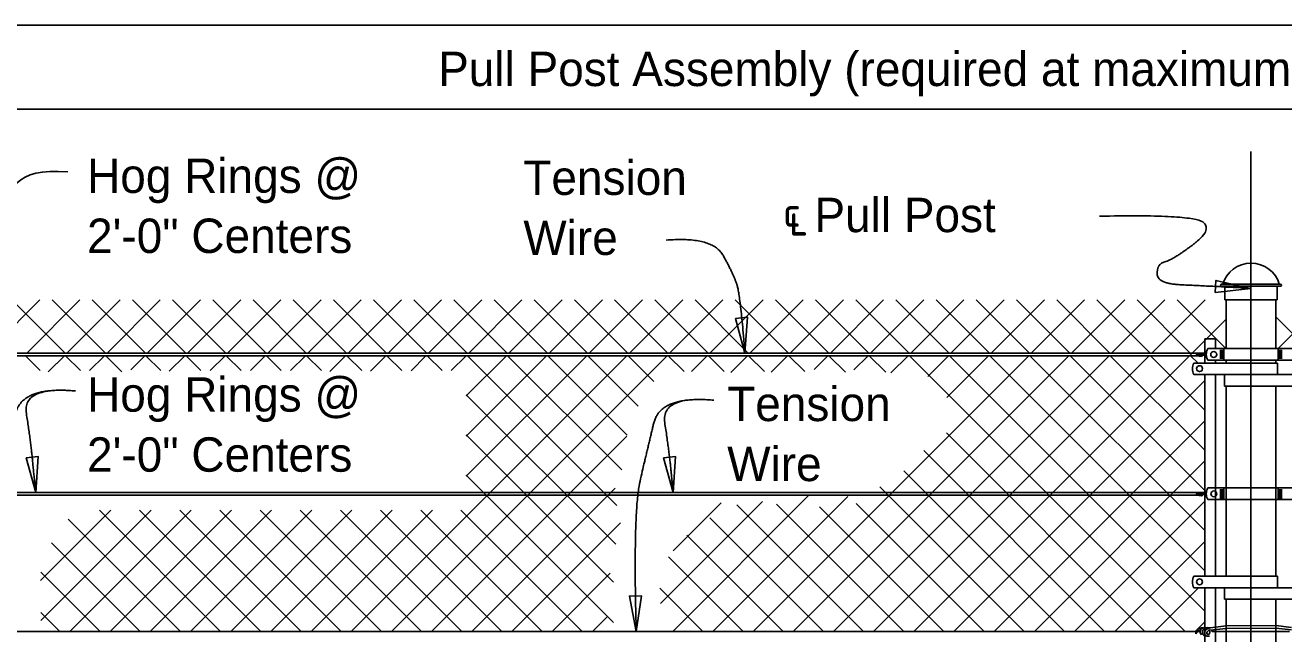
# Model space of a CAD drawing. Extents: x 0 to 41.2, y 0 to 26.
# Drawn here: x 5.02 to 12.4, y 22.39 to 25.96 of the extents above; entities that cross this region are included whole.
import ezdxf

# ---------------------------------------------------------------- set-up
doc = ezdxf.new("R2010")
doc.units = 0
for name, color, linetype in [('ActivePts-ConstElements', 7, 'Continuous'), ('CL_Major', 7, 'Continuous'), ('Dimension', 7, 'Continuous'), ('Miscellaneous', 7, 'Continuous'), ('Miscellaneous1', 7, 'Continuous'), ('SteelMisc', 7, 'Continuous'), ('SteelMisc_h', 7, 'Continuous'), ('TextStructures', 7, 'Continuous')]:
    doc.layers.add(name, color=color, linetype=linetype)

msp = doc.modelspace()

# ---------------------------------------------------------------- linework, layer by layer
at = {"layer": 'ActivePts-ConstElements'}
msp.add_lwpolyline([(0, 0), (41.2106, 0), (41.2106, 25.96), (0, 25.96)], close=True, dxfattribs=at)
at = {"layer": 'CL_Major'}
msp.add_line((12.2062, 25.2199), (12.2062, 14.8548), dxfattribs=at)
at = {"layer": 'Dimension'}
msp.add_line((2.2062, 25.4682), (22.2062, 25.4682), dxfattribs=at)
for points in [[(12.2062, 24.4166), (12.0002, 24.4632), (11.9964, 24.3927)], [(9.238, 24.0366), (9.2538, 24.2472), (9.1835, 24.2406)], [(5.0788, 23.219), (5.0926, 23.4298), (5.0224, 23.4226)], [(8.8174, 23.219), (8.8313, 23.4298), (8.7611, 23.4226)], [(8.6004, 22.4048), (8.6312, 22.6137), (8.5607, 22.6122)]]:
    msp.add_lwpolyline(points, close=True, dxfattribs=at)
for points, degree in [([(5.2657, 25.0995), (4.9524, 25.1279), (4.8838, 24.8459), (4.8116, 24.5363), (4.8088, 24.0365)], 3), ([(11.3168, 24.8403), (11.8625, 24.8501), (11.985, 24.7612), (11.7408, 24.5799), (11.6559, 24.5616), (11.6559, 24.4437), (11.934, 24.4315), (12.2063, 24.4166)], 2), ([(8.7761, 24.6996), (9.0478, 24.722), (9.174, 24.4948), (9.2108, 24.3733), (9.238, 24.0365)], 2), ([(5.3115, 23.815), (4.9982, 23.8433), (4.9198, 23.5211), (4.8367, 23.1628), (4.8566, 22.4048)], 2), ([(5.3115, 23.815), (4.9982, 23.8433), (5.0481, 23.5211), (5.0667, 23.326), (5.0788, 23.219)], 2), ([(9.0561, 23.7607), (8.7428, 23.789), (8.6644, 23.4668), (8.5813, 23.1085), (8.6004, 22.4048)], 2), ([(9.0561, 23.7607), (8.7428, 23.789), (8.7927, 23.4668), (8.8113, 23.2717), (8.8174, 23.219)], 2)]:
    msp.add_open_spline(points, degree=degree, dxfattribs=at)
at = {"layer": 'Miscellaneous'}
for p, q in [((5.1017, 24.349), (4.7948, 24.0422)), ((5.2507, 24.0365), (4.9382, 24.349)), ((5.3374, 24.349), (5.0249, 24.0365)), ((5.4864, 24.0365), (5.1739, 24.349)), ((5.5731, 24.349), (5.2606, 24.0365)), ((5.7221, 24.0365), (5.4096, 24.349)), ((5.8088, 24.349), (5.4963, 24.0365)), ((5.9579, 24.0365), (5.6453, 24.349)), ((6.0445, 24.349), (5.732, 24.0365)), ((6.1936, 24.0365), (5.881, 24.349)), ((6.2802, 24.349), (5.9677, 24.0365)), ((6.4293, 24.0365), (6.1167, 24.349)), ((6.5159, 24.349), (6.2034, 24.0365)), ((6.665, 24.0365), (6.3524, 24.349)), ((6.7516, 24.349), (6.4391, 24.0365)), ((6.9007, 24.0365), (6.5881, 24.349)), ((6.9873, 24.349), (6.6748, 24.0365)), ((7.1364, 24.0365), (6.8238, 24.349)), ((7.223, 24.349), (6.9105, 24.0365)), ((7.3721, 24.0365), (7.0595, 24.349)), ((7.4587, 24.349), (7.1462, 24.0365)), ((7.6078, 24.0365), (7.2952, 24.349)), ((7.6944, 24.349), (7.3819, 24.0365)), ((7.8435, 24.0365), (7.5309, 24.349)), ((7.9301, 24.349), (7.6176, 24.0365)), ((8.0792, 24.0365), (7.7666, 24.349)), ((8.1658, 24.349), (7.8533, 24.0365)), ((8.3149, 24.0365), (8.0023, 24.349)), ((8.4015, 24.349), (8.089, 24.0365)), ((8.5506, 24.0365), (8.238, 24.349)), ((8.6372, 24.349), (8.3247, 24.0365)), ((8.7863, 24.0365), (8.4737, 24.349)), ((8.8729, 24.349), (8.5604, 24.0365)), ((9.022, 24.0365), (8.7094, 24.349)), ((9.1086, 24.349), (8.7961, 24.0365)), ((9.2577, 24.0365), (8.9451, 24.349)), ((9.3443, 24.349), (9.0318, 24.0365)), ((9.4934, 24.0365), (9.1808, 24.349)), ((9.58, 24.349), (9.2675, 24.0365)), ((9.7291, 24.0365), (9.4166, 24.349)), ((9.8157, 24.349), (9.5032, 24.0365)), ((9.9648, 24.0365), (9.6523, 24.349)), ((10.0514, 24.349), (9.7389, 24.0365)), ((10.2005, 24.0365), (9.888, 24.349)), ((10.2871, 24.349), (9.9746, 24.0365)), ((10.4362, 24.0365), (10.1237, 24.349)), ((10.5228, 24.349), (10.2103, 24.0365)), ((10.6719, 24.0365), (10.3594, 24.349)), ((10.7585, 24.349), (10.446, 24.0365)), ((10.9076, 24.0365), (10.5951, 24.349)), ((10.9942, 24.349), (10.6817, 24.0365)), ((11.1433, 24.0365), (10.8308, 24.349)), ((11.2299, 24.349), (10.9174, 24.0365)), ((11.379, 24.0365), (11.0665, 24.349)), ((11.4657, 24.349), (11.1531, 24.0365)), ((11.6147, 24.0365), (11.3022, 24.349)), ((11.7014, 24.349), (11.3888, 24.0365)), ((11.8504, 24.0365), (11.5379, 24.349)), ((11.9371, 24.349), (11.6245, 24.0365)), ((12.0603, 24.0623), (11.7736, 24.349)), ((12.3656, 24.0631), (12.6516, 24.349)), ((12.0603, 24.2366), (10.2285, 22.4048)), ((12.352, 24.2494), (12.5649, 24.0365)), ((5.1043, 23.9344), (5.017, 24.0218)), ((5.2458, 24.0218), (5.1507, 23.9266)), ((5.2458, 24.0218), (5.1585, 23.9344)), ((5.34, 23.9344), (5.2527, 24.0218)), ((5.4815, 24.0218), (5.3942, 23.9344)), ((5.5828, 23.9273), (5.4884, 24.0218)), ((5.7172, 24.0218), (5.6353, 23.9398)), ((5.8114, 23.9344), (5.7241, 24.0218)), ((5.9529, 24.0218), (5.8616, 23.9304)), ((6.0471, 23.9344), (5.9598, 24.0218)), ((6.1886, 24.0218), (6.1013, 23.9344)), ((6.2828, 23.9344), (6.1955, 24.0218)), ((6.4243, 24.0218), (6.337, 23.9344)), ((6.5185, 23.9344), (6.4312, 24.0218)), ((6.66, 24.0218), (6.5727, 23.9344)), ((6.7542, 23.9344), (6.6669, 24.0218)), ((6.8957, 24.0218), (6.8036, 23.9297)), ((6.9899, 23.9344), (6.9026, 24.0218)), ((8.5456, 24.0218), (6.9286, 22.4048)), ((7.1314, 24.0218), (7.0414, 23.9318)), ((7.2256, 23.9344), (7.1383, 24.0218)), ((8.7813, 24.0218), (7.1643, 22.4048)), ((7.3671, 24.0218), (7.2793, 23.9339)), ((7.4613, 23.9344), (7.374, 24.0218)), ((7.6028, 24.0218), (7.5155, 23.9344)), ((8.0742, 24.0218), (7.6029, 23.5504)), ((7.8385, 24.0218), (7.6029, 23.7861)), ((8.3099, 24.0218), (7.6029, 23.3147)), ((8.4874, 23.1441), (7.6097, 24.0218)), ((8.515, 23.3522), (7.8454, 24.0218)), ((8.5473, 23.5556), (8.0811, 24.0218)), ((8.6123, 23.7263), (8.3168, 24.0218)), ((8.7037, 23.8706), (8.5525, 24.0218)), ((8.8813, 23.9287), (8.7882, 24.0218)), ((9.017, 24.0218), (8.9244, 23.9291)), ((9.117, 23.9287), (9.0239, 24.0218)), ((9.2527, 24.0218), (9.1549, 23.9239)), ((9.3527, 23.9287), (9.2596, 24.0218)), ((9.4884, 24.0218), (9.3919, 23.9252)), ((9.5884, 23.9287), (9.4953, 24.0218)), ((9.7242, 24.0218), (9.6441, 23.9417)), ((9.8278, 23.925), (9.731, 24.0218)), ((11.3741, 24.0218), (9.7571, 22.4048)), ((9.9599, 24.0218), (9.877, 23.9389)), ((10.0639, 23.9246), (9.9668, 24.0218)), ((11.6098, 24.0218), (9.9928, 22.4048)), ((10.1956, 24.0218), (10.0944, 23.9206)), ((11.8195, 22.4048), (10.2025, 24.0218)), ((10.9027, 24.0218), (10.2239, 23.343)), ((10.4313, 24.0218), (10.3102, 23.9007)), ((10.667, 24.0218), (10.4218, 23.7766)), ((11.1384, 24.0218), (10.4313, 23.3147)), ((11.9353, 22.5246), (10.4382, 24.0218)), ((11.9353, 22.7603), (10.6739, 24.0218)), ((11.9353, 22.996), (10.9096, 24.0218)), ((11.9353, 23.2317), (11.1453, 24.0218)), ((11.9353, 23.4674), (11.381, 24.0218)), ((11.9353, 23.7031), (11.6167, 24.0218)), ((11.8956, 23.9786), (11.8524, 24.0218)), ((11.9353, 23.8759), (10.4642, 22.4048)), ((8.48, 22.9158), (7.6029, 23.7929)), ((11.9353, 23.6402), (10.6999, 22.4048)), ((8.4664, 22.6937), (7.6029, 23.5572)), ((11.5838, 22.4048), (10.42, 23.5685)), ((8.5456, 23.5503), (7.4, 22.4048)), ((11.348, 22.4048), (10.2867, 23.4661)), ((11.9353, 23.4045), (10.9356, 22.4048)), ((10.2239, 23.343), (9.2857, 22.4048)), ((11.1123, 22.4048), (10.1704, 23.3467)), ((8.4668, 22.4576), (7.6029, 23.3215)), ((10.4313, 23.3147), (9.5214, 22.4048)), ((8.4762, 23.2452), (7.6357, 22.4048)), ((9.615, 23.2055), (8.8143, 22.4048)), ((9.8417, 23.1965), (9.05, 22.4048)), ((10.8766, 22.4048), (10.0292, 23.2522)), ((5.5188, 23.1163), (5.1055, 22.7029)), ((5.7545, 23.1163), (5.1078, 22.4696)), ((5.9902, 23.1163), (5.2787, 22.4048)), ((6.1626, 22.4048), (5.4511, 23.1163)), ((6.2259, 23.1163), (5.5144, 22.4048)), ((6.3983, 22.4048), (5.6868, 23.1163)), ((6.4616, 23.1163), (5.7501, 22.4048)), ((6.634, 22.4048), (5.9225, 23.1163)), ((6.6973, 23.1163), (5.9858, 22.4048)), ((6.8697, 22.4048), (6.1582, 23.1163)), ((6.933, 23.1163), (6.2215, 22.4048)), ((7.1054, 22.4048), (6.3939, 23.1163)), ((7.1687, 23.1163), (6.4572, 22.4048)), ((7.3411, 22.4048), (6.6296, 23.1163)), ((7.4044, 23.1163), (6.6929, 22.4048)), ((7.5768, 22.4048), (6.8653, 23.1163)), ((7.8125, 22.4048), (7.101, 23.1163)), ((8.0482, 22.4048), (7.3367, 23.1163)), ((8.2839, 22.4048), (7.5724, 23.1163)), ((9.3401, 23.1663), (8.7428, 22.569)), ((9.0978, 23.1597), (8.8163, 22.8782)), ((9.9338, 22.4048), (9.1908, 23.1477)), ((10.1695, 22.4048), (9.4222, 23.1521)), ((10.4052, 22.4048), (9.6754, 23.1346)), ((10.6409, 22.4048), (9.8912, 23.1545)), ((11.9353, 23.1688), (11.1713, 22.4048)), ((5.9269, 22.4048), (5.2677, 23.064)), ((8.5075, 23.0408), (7.8714, 22.4048)), ((9.6981, 22.4048), (9.0326, 23.0703)), ((9.4624, 22.4048), (8.8976, 22.9695)), ((5.6912, 22.4048), (5.1708, 22.9251)), ((11.9353, 22.9331), (11.407, 22.4048)), ((9.2267, 22.4048), (8.7891, 22.8423)), ((5.4555, 22.4048), (5.1078, 22.7524)), ((8.4481, 22.7457), (8.1071, 22.4048)), ((8.991, 22.4048), (8.7382, 22.6576)), ((11.8989, 22.6609), (11.6427, 22.4048)), ((5.2198, 22.4048), (5.1078, 22.5167)), ((8.4312, 22.4931), (8.3429, 22.4048)), ((11.9353, 22.4617), (11.8784, 22.4048))]:
    msp.add_line(p, q, dxfattribs=at)
at = {"layer": 'Miscellaneous1'}
msp.add_lwpolyline([(0, 25.96), (41.2106, 25.96), (41.2106, 0), (0, 0)], close=True, dxfattribs=at)
at = {"layer": 'SteelMisc'}
for p, q in [((12.0339, 24.441), (12.3785, 24.441)), ((12.3785, 24.4288), (12.0339, 24.4288)), ((12.0521, 24.349), (12.0521, 24.4288)), ((12.3602, 24.349), (12.3602, 24.4288)), ((12.3602, 24.349), (12.0521, 24.349)), ((12.0603, 24.0636), (12.0603, 24.349)), ((12.352, 24.0636), (12.352, 24.349)), ((11.9353, 24.0396), (11.9353, 24.1198)), ((11.9978, 24.1198), (11.9353, 24.1198)), ((11.9978, 24.0636), (11.9978, 24.1198)), ((11.9243, 24.0218), (2.5005, 24.0218)), ((11.9229, 24.0365), (2.5271, 24.0365)), ((11.9443, 24.0207), (11.9107, 24.0264)), ((11.9439, 24.0255), (11.9141, 24.0304)), ((11.945, 24.0412), (11.9157, 24.0366)), ((11.9442, 24.0362), (11.9182, 24.0321)), ((11.9353, 24.0396), (11.9353, 23.9786)), ((11.9353, 24.0347), (11.9353, 24.0269)), ((12.362, 24.0637), (11.9522, 24.0637)), ((12.362, 23.9959), (11.9527, 23.9959)), ((11.9978, 23.9959), (11.9978, 23.9786)), ((12.0236, 24.0528), (12.0466, 24.0528)), ((12.0236, 24.0473), (12.0466, 24.0473)), ((12.0236, 24.0393), (12.0466, 24.0393)), ((12.0236, 24.0337), (12.0466, 24.0337)), ((12.0236, 24.0257), (12.0466, 24.0257)), ((12.0236, 24.0202), (12.0466, 24.0202)), ((12.0236, 24.0122), (12.0466, 24.0122)), ((12.0236, 24.0066), (12.0466, 24.0066)), ((12.0466, 23.9959), (12.0466, 24.0637)), ((12.0505, 24.0637), (12.4602, 24.0637)), ((12.0505, 23.9959), (12.4598, 23.9959)), ((12.0604, 23.9786), (12.0604, 23.9959)), ((12.3521, 23.9786), (12.3521, 23.9959)), ((12.3886, 24.0528), (12.3657, 24.0528)), ((12.3886, 24.0473), (12.3657, 24.0473)), ((12.3886, 24.0393), (12.3657, 24.0393)), ((12.3886, 24.0337), (12.3657, 24.0337)), ((12.3886, 24.0257), (12.3657, 24.0257)), ((12.3886, 24.0202), (12.3657, 24.0202)), ((12.3886, 24.0122), (12.3657, 24.0122)), ((12.3886, 24.0066), (12.3657, 24.0066)), ((12.3658, 23.9959), (12.3658, 24.0637)), ((12.3621, 23.9786), (11.8709, 23.9786)), ((12.3621, 23.9786), (12.3621, 23.9109)), ((12.3621, 23.9109), (11.8717, 23.9109)), ((11.9353, 23.9109), (11.9353, 22.7286)), ((11.9978, 23.9109), (11.9978, 22.7286)), ((12.0505, 23.9109), (12.0505, 23.8433)), ((12.0505, 23.9109), (12.5416, 23.9109)), ((12.0505, 23.8433), (12.5408, 23.8433)), ((12.0604, 22.7286), (12.0604, 23.8433)), ((12.3521, 22.7286), (12.3521, 23.8433)), ((11.9244, 23.2043), (2.5006, 23.2043)), ((11.9231, 23.219), (2.5273, 23.219)), ((11.9445, 23.2033), (11.9109, 23.2089)), ((11.9441, 23.2081), (11.9143, 23.213)), ((11.9451, 23.2237), (11.9159, 23.2191)), ((11.9444, 23.2187), (11.9184, 23.2146)), ((11.9354, 23.2172), (11.9354, 23.2094)), ((12.3622, 23.2462), (11.9524, 23.2462)), ((12.0238, 23.2354), (12.0468, 23.2354)), ((12.0238, 23.2298), (12.0468, 23.2298)), ((12.0238, 23.2218), (12.0468, 23.2218)), ((12.0238, 23.2163), (12.0468, 23.2163)), ((12.0238, 23.2083), (12.0468, 23.2083)), ((12.0238, 23.2027), (12.0468, 23.2027)), ((12.0238, 23.1947), (12.0468, 23.1947)), ((12.0238, 23.1892), (12.0468, 23.1892)), ((12.0468, 23.1785), (12.0468, 23.2462)), ((12.0506, 23.2462), (12.4603, 23.2462)), ((12.3888, 23.2354), (12.3658, 23.2354)), ((12.3888, 23.2298), (12.3658, 23.2298)), ((12.3888, 23.2218), (12.3658, 23.2218)), ((12.3888, 23.2163), (12.3658, 23.2163)), ((12.3888, 23.2083), (12.3658, 23.2083)), ((12.3888, 23.2027), (12.3658, 23.2027)), ((12.3888, 23.1947), (12.3658, 23.1947)), ((12.3888, 23.1892), (12.3658, 23.1892)), ((12.366, 23.1785), (12.366, 23.2462)), ((12.3622, 23.1785), (11.9528, 23.1785)), ((12.0506, 23.1785), (12.46, 23.1785)), ((12.3621, 22.7286), (11.8709, 22.7286)), ((12.3621, 22.7286), (12.3621, 22.6609)), ((12.3621, 22.6609), (11.8717, 22.6609)), ((11.9353, 21.4785), (11.9353, 22.6609)), ((11.9978, 21.4785), (11.9978, 22.6609)), ((12.0505, 22.6609), (12.0505, 22.5933)), ((12.0505, 22.6609), (12.5416, 22.6609)), ((12.0505, 22.5933), (12.5408, 22.5933)), ((12.0604, 21.4785), (12.0604, 22.5933)), ((12.3521, 21.4785), (12.3521, 22.5933)), ((2.5108, 22.4048), (11.8852, 22.4048)), ((11.8951, 22.4048), (11.9083, 22.4048)), ((12.0603, 22.4374), (11.9675, 22.4257)), ((12.0603, 22.4229), (11.9675, 22.4132)), ((11.9782, 22.4048), (12.0603, 22.4048)), ((12.0603, 22.4374), (12.3515, 22.4391)), ((12.0603, 22.4229), (12.3515, 22.4245)), ((12.3515, 22.4391), (12.4435, 22.4275)), ((12.3515, 22.4245), (12.4434, 22.415)), ((12.352, 22.4048), (12.4324, 22.4048))]:
    msp.add_line(p, q, dxfattribs=at)
for centre, start, end in [((12.034, 24.4347), 91.1647, 268.8353), ((12.3783, 24.4347), 271.1647, 88.8353)]:
    msp.add_arc(centre, 0.00613, start, end, dxfattribs=at)
for centre, major_axis, ratio, start_param, end_param in [((12.2068, 24.4), (0.1711, 0), 0.957868, 0.252602, 2.888574), ((11.908, 24.0082), (-0.0274, 0), 0.957868, 5.133531, 5.654664), ((11.9, 24.0233), (0.0142, 0), 0.957868, 1.486836, 3.141593), ((11.9052, 24.0278), (-0.00944, 0), 0.957868, 6.009018, 8.249874), ((11.9048, 24.0288), (0.00872, 0), 0.957868, 1.29026, 2.959852), ((11.9048, 24.0288), (0.00503, 0), 0.92697, 1.570796, 4.502291), ((11.9113, 24.0283), (0.00872, 0), 0.957868, 1.29026, 4.182385), ((11.917, 24.0274), (-0.0115, -0.0041), 0.737732, 4.35367, 7.47816), ((11.9157, 24.0259), (-0.00527, 0), 0.957868, 5.22362, 7.507542), ((11.9136, 24.025), (-0.00301, 0), 0.957868, 6.141288, 6.278592), ((11.9189, 24.0225), (-0.00982, 0), 0.957868, 4.777514, 5.62749), ((11.9136, 24.025), (-0.00301, 0), 0.957868, 1.11255, 2.999696), ((11.9129, 24.0272), (0.00453, 0), 0.957868, 0.731188, 1.133458), ((11.913, 24.0267), (0.0095, 0), 0.957868, 5.011765, 6.030719), ((11.913, 24.0267), (0.0095, 0), 0.957868, 0.230606, 0.609214), ((12.0215, 24.03), (-0.0776, 0), 0.957868, 5.81433, 6.762456), ((11.9404, 23.9454), (-0.0776, 0), 0.957868, 5.821213, 6.765127), ((11.9082, 23.1908), (-0.0274, 0), 0.957868, 5.133531, 5.654664), ((11.9002, 23.2058), (0.0142, 0), 0.957868, 1.486836, 3.141593), ((11.9054, 23.2104), (-0.00944, 0), 0.957868, 6.009018, 8.249874), ((11.9049, 23.2113), (0.00872, 0), 0.957868, 1.29026, 2.959852), ((11.9049, 23.2113), (0.00503, 0), 0.92697, 1.570796, 4.502291), ((11.9115, 23.2108), (0.00872, 0), 0.957868, 1.29026, 4.182385), ((11.9172, 23.2099), (-0.0115, -0.0041), 0.737732, 4.35367, 7.47816), ((11.9159, 23.2084), (-0.00527, 0), 0.957868, 5.22362, 7.507542), ((11.9138, 23.2075), (-0.00301, 0), 0.957868, 6.141288, 6.278592), ((11.9191, 23.205), (-0.00982, 0), 0.957868, 4.777514, 5.62749), ((11.9138, 23.2075), (-0.00301, 0), 0.957868, 1.11255, 2.999696), ((11.9131, 23.2097), (0.00453, 0), 0.957868, 0.731188, 1.133458), ((11.9132, 23.2092), (0.0095, 0), 0.957868, 5.011765, 6.030719), ((11.9132, 23.2092), (0.0095, 0), 0.957868, 0.230606, 0.609214), ((12.0216, 23.2125), (-0.0776, 0), 0.957868, 5.81433, 6.762456), ((11.9404, 22.6954), (-0.0776, 0), 0.957868, 5.821213, 6.765127), ((11.9194, 22.3905), (0.0373, 0), 0.957868, 1.427863, 3.108042), ((11.9405, 22.3508), (-0.0724, 0), 0.957868, 5.133134, 5.652106), ((11.9331, 22.4025), (-0.0249, 0), 0.957868, 5.913851, 7.104804), ((11.9319, 22.405), (0.023, 0), 0.957868, 1.234085, 2.861055), ((11.9507, 22.3996), (0.0295, 0), 0.957868, 1.132635, 3.996184), ((11.9641, 22.4014), (-0.0303, -0.0108), 0.724765, 4.35367, 6.224248), ((11.954, 22.3928), (0.0206, -0.0021), 0.798607, 3.319436, 5.220153), ((11.9608, 22.3973), (-0.0139, 0), 0.957868, 5.822914, 6.485782), ((11.9552, 22.3949), (-0.00795, 0), 0.957868, 0.039428, 2.999692), ((11.9692, 22.3885), (-0.0259, 0), 0.957868, 4.777514, 5.646371), ((11.9535, 22.4007), (0.0119, 0), 0.957868, 5.725876, 7.416677), ((11.9535, 22.4007), (0.0119, 0), 0.957868, 5.639684, 5.723117), ((11.9537, 22.3995), (0.0251, 0), 0.957868, 0.221743, 0.642584)]:
    msp.add_ellipse(centre, major_axis=major_axis, ratio=ratio, start_param=start_param, end_param=end_param, dxfattribs=at)
for centre, major_axis in [((11.9881, 24.0291), (0.0178, 0)), ((11.9045, 23.9458), (0.0177, 0)), ((11.9883, 23.2117), (0.0178, 0)), ((11.9045, 22.6958), (0.0177, 0))]:
    msp.add_ellipse(centre, major_axis=major_axis, ratio=0.957868, dxfattribs=at)
at = {"layer": 'SteelMisc_h'}
msp.add_line((12.0603, 22.4048), (12.352, 22.4048), dxfattribs=at)

# ---------------------------------------------------------------- texts
at = {"layer": 'Dimension'}
for s, p in [('Hog Rings @ ', (5.3791, 24.9762)), ('Tension ', (7.9381, 24.9647)), ('2\'-0" Centers', (5.3791, 24.6242)), ('Wire ', (7.9381, 24.6127)), ('Hog Rings @ ', (5.3792, 23.6935)), ('Tension ', (9.1338, 23.6384)), ('2\'-0" Centers', (5.3792, 23.3415)), ('Wire ', (9.1338, 23.2864))]:
    msp.add_text(s, height=0.2016, dxfattribs=at).set_placement(p)
at = {"layer": 'TextStructures'}
for s, p in [('Pull Post Assembly (required at maximum intervals of 500\'-0")', (7.4383, 25.603)), ('℄ Pull Post', (9.4613, 24.7464))]:
    msp.add_text(s, height=0.2016, dxfattribs=at).set_placement(p)

doc.saveas('drawing.dxf')
